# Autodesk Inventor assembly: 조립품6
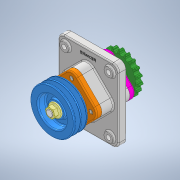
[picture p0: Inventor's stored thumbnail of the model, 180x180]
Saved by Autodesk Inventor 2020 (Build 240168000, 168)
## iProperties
Created: 2021-07
Part Number: 조립품6
Document SubType Name: Assembly
Designer: Owner
Author: Owner
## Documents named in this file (16)
- C:\Users\Owner\Desktop\710707V1002\조립품6.iam
- C:\Users\Owner\Desktop\710707V1002\본체.ipt
- C:\Users\Owner\Desktop\710707V1002\M16 너트.ipt
- C:\Users\Owner\Desktop\710707V1002\V-벨트풀리.ipt
- C:\Users\Owner\Desktop\710707V1002\멈춤나사 M4.ipt
- C:\Users\Owner\Desktop\710707V1002\베어링 6206.ipt
- C:\Users\Owner\Desktop\710707V1002\볼트 M6.ipt
- C:\Users\Owner\Desktop\710707V1002\부시.ipt
- C:\Users\Owner\Desktop\710707V1002\오일실 30x42x8.ipt
- C:\Users\Owner\Desktop\710707V1002\오일실 30x45x8.ipt
- C:\Users\Owner\Desktop\710707V1002\체인 스프로킷.ipt
- C:\Users\Owner\Desktop\710707V1002\축.ipt
- C:\Users\Owner\Desktop\710707V1002\커버A.ipt
- C:\Users\Owner\Desktop\710707V1002\커버B.ipt
- C:\Users\Owner\Desktop\710707V1002\키 6x6x18.ipt
- C:\Users\Owner\Desktop\710707V1002\키 6x6x20.ipt
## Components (2 placed, 2 different names)
1. M16 너트:1
2. V-벨트풀리:1
